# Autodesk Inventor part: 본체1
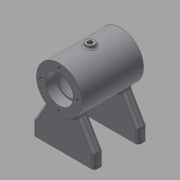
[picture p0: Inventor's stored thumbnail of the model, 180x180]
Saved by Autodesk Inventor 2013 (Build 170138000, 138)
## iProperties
Created: 2018-05
Part Number: 본체1
Material: 일반
Document SubType Name: Modeling
Designer: dgall
Density: 1 g/cm^3
Author: dgall
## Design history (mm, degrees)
sketch "스케치1"
  geometry: L1 (-35, 16)-(-35, 26); L2 (-35, 26)-(35, 26); L3 (35, 26)-(35, 16); L4 (35, 16)-(23.3, 16); L5 (23, 15.7)-(23, 14); L6 (23, 14)-(21, 14); L7 (21, 14)-(21, 18); L8 (18, 21)-(-18, 21); L9 (-21, 18)-(-21, 14); L10 (-21, 14)-(-23, 14); L11 (-23, 14)-(-23, 15.7); L12 (-23.3, 16)-(-35, 16); L13 (-37.023, 0)-(37.902, 0); A1 r 3 centre (-18, 18) between (-18, 21) and (-21, 18); A2 r 3 centre (18, 18) between (21, 18) and (18, 21); A3 r 0.3 centre (-23.3, 15.7) between (-23, 15.7) and (-23.3, 16); A4 r 0.3 centre (23.3, 15.7) between (23.3, 16) and (23, 15.7); 5 further points
  constraints: 26 end point, 9 parallel, 9 point on line, 8 point on circle, 8 tangent, 4 centre point, 3 perpendicular, 2 equal radius, 1 vertical
  dimensions: "d0" = 70 distance between parallel lines of L3 L1; "d2" = 35 distance from line of point (0, 0) L1; "d3" = 52 diameter of L2 L13; "d4" = 42 diameter of L8 L13; "d5" = 42 distance of point (21, 21) point (-21, 21); "d6" = 28 diameter of L10 L13; "d7" = 32 diameter of L12 L13; "d8" = 12 distance of point (-23, 16) L1.start; "d9" = 12 distance of L3.end point (23, 16); "d10" = 2 distance of L5.end L6.end; "d11" = 32 diameter of L4 L13; "d12" = 28 diameter of L6 L13; "d13" = 3 radius of A1; "d99" = 0.3 radius of A3
revolve "회전1" sketch "스케치1" stored, may be unused: angle "d14" = 90 deg
node "작업 평면1"
node "작업 평면2"
node "작업 평면4"
  node "작업 평면3"
sketch "스케치4"
  geometry: C1 r 5 at (0, 0); 1 further point
  constraints: 1 centre point, 1 coincident
  dimensions: "d40" = 10 diameter of C1
extrude "돌출3" join sketch "스케치4" stored distance "d42" = 10; taper "d43" = 0 deg
sketch "스케치5"
  geometry: C1 r 5 at (0, 0) reference; C2 r 3 at (0, 0)
  constraints: 1 centre point, 1 coincident
  dimensions: "d44" = 6 diameter of C2
hole "구멍1" sketch "스케치5" at (0, 0) diameter "d46" = 5.188; stored, may be unused: countersink angle "d50" = 90 deg, drill point angle "d52" = 118 deg; dims "d47" = 6, "d48" = 4, "d49" = 2, "d51" = 8
fillet "모깎기1" dims "d53" = 2
sketch "스케치7" dims "d69" = 42
  geometry: L1 (0, 0)-(-21, 0); C1 r 16 at (0, 0) reference; C2 r 26 at (0, 0) reference; C3 r 2 at (-21, 0); C4 r 2 at (0, -21); C5 r 2 at (21, 0); C6 r 2 at (0, 21)
  constraints: 4 centre point, 2 coincident, 2 end point, 1 horizontal, 1 horizontal alignment, 11 other
  dimensions: "d71" = 4 diameter of C3; "d74" = 360 deg dimension on C1.centre C3.centre (derived)
hole "구멍3" sketch "스케치7" at (-21, 0), (0, 21), (21, 0), (0, -21) diameter "d76" = 3.242; stored, may be unused: countersink angle "d80" = 90 deg, drill point angle "d82" = 118 deg; dims "d77" = 8, "d78" = 4, "d79" = 2, "d81" = 10
node "작업 평면6"
  node "작업 평면5"
sketch "스케치9"
  geometry: C1 r 6 at (0, 0); 1 further point
  constraints: 1 centre point, 1 coincident
  dimensions: "d85" = 12 diameter of C1
extrude "돌출4" join sketch "스케치9" stored distance "d87" = 10; taper "d88" = 0 deg
sketch "스케치10"
  geometry: C1 r 6 at (0, 0) reference; C2 r 3 at (0, 0)
  constraints: 1 centre point, 1 coincident
  dimensions: "d89" = 6 diameter of C2
hole "구멍4" sketch "스케치10" at (0, 0) diameter "d91" = 5.242; stored, may be unused: countersink angle "d95" = 90 deg, drill point angle "d97" = 118 deg; dims "d92" = 8, "d93" = 4, "d94" = 2, "d96" = 10
fillet "모깎기4" dims "d98" = 2
node "작업 평면8"
sketch "스케치12"
  geometry: L1 (-35, -65)-(35, -65); L2 (-35, -65)-(-35, -50); L3 (35, -65)-(35, -50); L4 (-35, -50)-(-17.325, -19.386); L5 (35, -50)-(17.325, -19.386); A1 r 26 centre (0, 0) between (-17.325, -19.386) and (17.325, -19.386) reference; 1 further point
  constraints: 10 end point, 2 point on circle, 1 horizontal, 1 parallel, 1 perpendicular
  dimensions: "d105" = 70 distance of L1.start L1.end; "d107" = 35 horizontal distance of L1.start point (0, 0); "d108" = 65 distance from line of L1 point (0, 0); "d109" = 15 distance of L1.start L2.end; "d110" = 15 distance of L1.end L3.end; "d111" = 30 deg angle of L4 L2; "d112" = 30 deg angle of L5 L3
extrude "돌출6" join sketch "스케치12" distance "d113" = 10; taper "d114" = 0 deg
sketch "스케치13"
  geometry: L1 (0, 70)-(0, 0) reference; C1 r 2.5 at (5, 55); C2 r 2.5 at (5, 15); 1 further point
  constraints: 2 centre point
  dimensions: "d115" = 5 diameter of C1; "d117" = 5 diameter of C2; "d118" = 5 distance from line of L1 C1.centre; "d119" = 5 distance from line of L1 C2.centre; "d120" = 20 vertical distance of point (-20, 35) C1.centre; "d121" = 20 vertical distance of point (-20, 35) C2.centre
hole "구멍5" sketch "스케치13" at (5, 15), (5, 55) diameter "d122" = 4.134; stored, may be unused: countersink angle "d126" = 90 deg, drill point angle "d128" = 118 deg; dims "d123" = 8, "d124" = 4, "d125" = 2, "d127" = 10
fillet "모깎기5" dims "d129" = 3
fillet "모깎기6" dims "d130" = 3
node "솔리드1"
mirror "대칭2"
mirror "대칭3"
mirror "대칭4"
other parameters: "d39" = 3, "d83" = 20 deg, "d84" = -29
